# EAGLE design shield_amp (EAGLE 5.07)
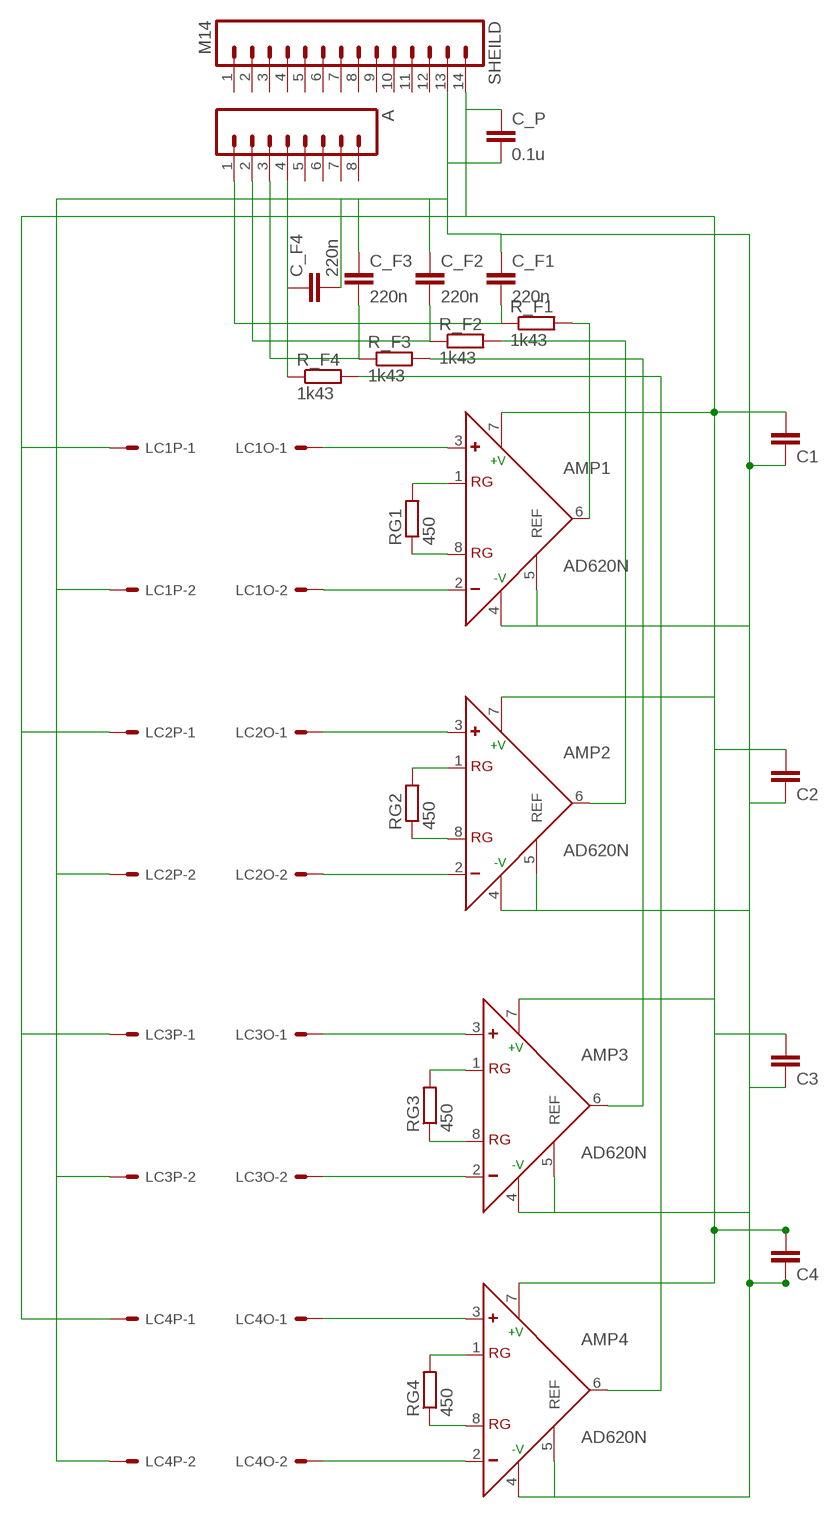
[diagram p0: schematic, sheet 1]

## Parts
A  M081X08  [1X08]
AMP1  AD620N  [DIL08]
AMP2  AD620N  [DIL08]
AMP3  AD620N  [DIL08]
AMP4  AD620N  [DIL08]
C1  C-EUC0603  [C0603]
C2  C-EUC0603  [C0603]
C3  C-EUC0603  [C0603]
C4  C-EUC0603  [C0603]
C_F1  220n  C-EU025-024X044  [C025-024X044]
C_F2  220n  C-EU025-024X044  [C025-024X044]
C_F3  220n  C-EU025-024X044  [C025-024X044]
C_F4  220n  C-EU025-024X044  [C025-024X044]
C_P  0.1u  C-EU025-024X044  [C025-024X044]
LC1O  87758-0216  [87758-0216]
LC1P  87758-0216  [87758-0216]
LC2O  87758-0216  [87758-0216]
LC2P  87758-0216  [87758-0216]
LC3O  87758-0216  [87758-0216]
LC3P  87758-0216  [87758-0216]
LC4O  87758-0216  [87758-0216]
LC4P  87758-0216  [87758-0216]
R_F1  1k43  R-EU_0207/7  [0207/7]
R_F2  1k43  R-EU_0207/7  [0207/7]
R_F3  1k43  R-EU_0207/7  [0207/7]
R_F4  1k43  R-EU_0207/7  [0207/7]
RG1  450  R-EU_0207/7  [0207/7]
RG2  450  R-EU_0207/7  [0207/7]
RG3  450  R-EU_0207/7  [0207/7]
RG4  450  R-EU_0207/7  [0207/7]
SHEILD  M14  [1X14]

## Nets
GND: AMP1.4(-V) AMP1.5(REF) AMP2.4(-V) AMP2.5(REF) AMP3.4(-V) AMP3.5(REF) AMP4.4(-V) AMP4.5(REF) C1.1 C2.1 C3.1 C4.1 C_F1.1 C_F2.1 C_F3.1 C_F4.2 C_P.2 LC1P.2 LC2P.2 LC3P.2 LC4P.2 SHEILD.13
N$1: AMP1.1(RG) RG1.2
N$2: AMP1.3(+) LC1O.1
N$3: AMP1.8(RG) RG1.1
N$4: AMP1.2(-) LC1O.2
N$5: AMP2.3(+) LC2O.1
N$6: AMP2.1(RG) RG2.2
N$7: AMP2.8(RG) RG2.1
N$8: AMP2.2(-) LC2O.2
N$9: AMP3.3(+) LC3O.1
N$10: AMP3.1(RG) RG3.2
N$11: AMP3.8(RG) RG3.1
N$12: AMP3.2(-) LC3O.2
N$13: AMP4.3(+) LC4O.1
N$14: AMP4.1(RG) RG4.2
N$15: AMP4.8(RG) RG4.1
N$16: AMP4.2(-) LC4O.2
N$17: AMP1.6(OUT) R_F1.2
N$18: AMP2.6(OUT) R_F2.2
N$19: AMP3.6(OUT) R_F3.2
N$20: AMP4.6(OUT) R_F4.2
N$21: AMP1.7(+V) AMP2.7(+V) AMP3.7(+V) AMP4.7(+V) C1.2 C2.2 C3.2 C4.2 C_P.1 LC1P.1 LC2P.1 LC3P.1 LC4P.1 SHEILD.14
N$22: A.3 C_F3.2 R_F3.1
N$23: A.1 C_F1.2 R_F1.1
N$25: A.2 C_F2.2 R_F2.1
N$26: A.4 C_F4.1 R_F4.1
Unconnected: A.5 A.6 A.7 A.8 SHEILD.1 SHEILD.2 SHEILD.3 SHEILD.4 SHEILD.5 SHEILD.6 SHEILD.7 SHEILD.8 SHEILD.9 SHEILD.10 SHEILD.11 SHEILD.12

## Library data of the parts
A = SparkFun:M08: Header 8 Standard 8-pin 0.1" header. Use with straight break away headers (SKU : PRT-00116), right angle break away headers (PRT-00553), swiss pins (PRT-00743), machine pins (PRT-00117), and female headers (PRT-00115).
AMP1-AMP4 = analog-devices:AD620: Low Cost, Low Power, Instrumentation Amplifier Source: http://www.analog.com/UploadedFiles/Data_Sheets/37793330023930AD620_e.pdf
C1-C4 C_F1-C_F4 C_P = resistor:C-EU: CAPACITOR, European symbol
LC1O LC1P LC2O LC2P LC3O LC3P LC4O LC4P = con-molex:87758-0216: 2 Pin - 2mm Dual Row Single Wafer, Vertical T/H HDR
R_F1-R_F4 RG1-RG4 = resistor:R-EU_: RESISTOR, European symbol
SHEILD = SparkFun:M14: Header 14 Standard 14-pin 0.1" header. Use with straight break away headers (SKU : PRT-00116), right angle break away headers (PRT-00553), swiss pins (PRT-00743), machine pins (PRT-00117), and female headers (PRT-00115).

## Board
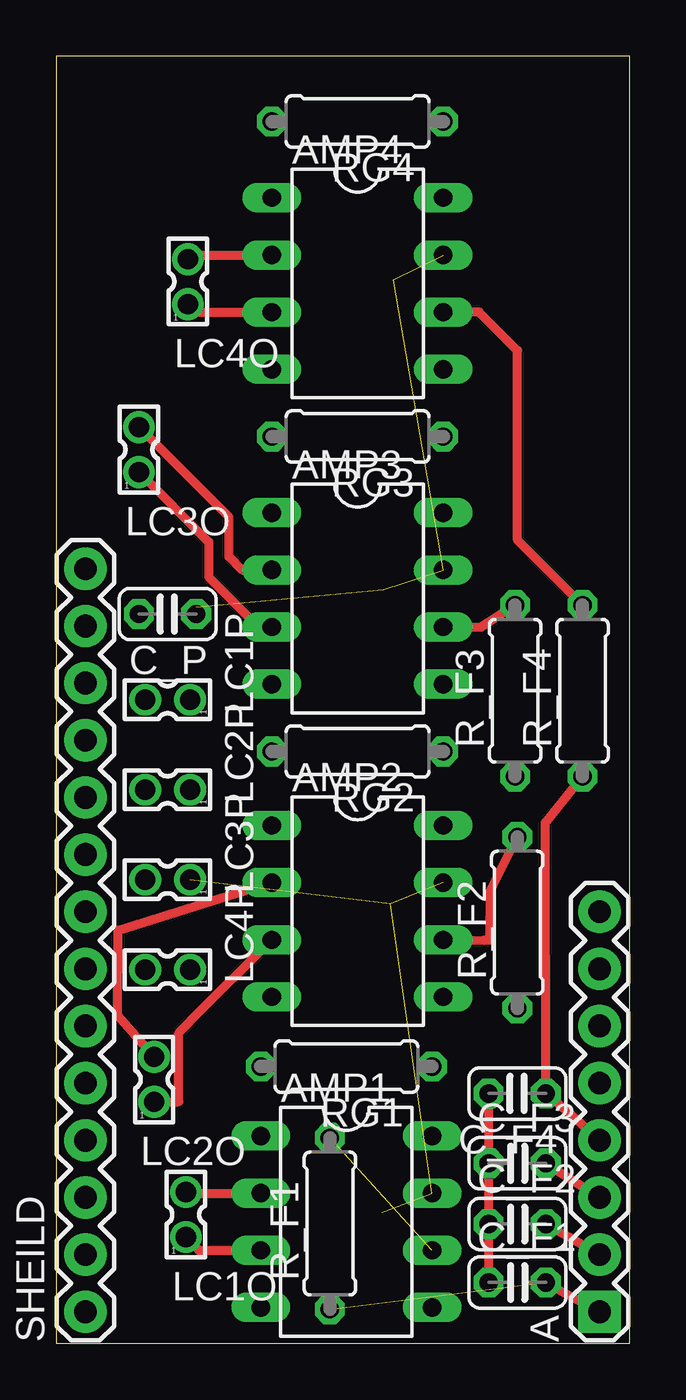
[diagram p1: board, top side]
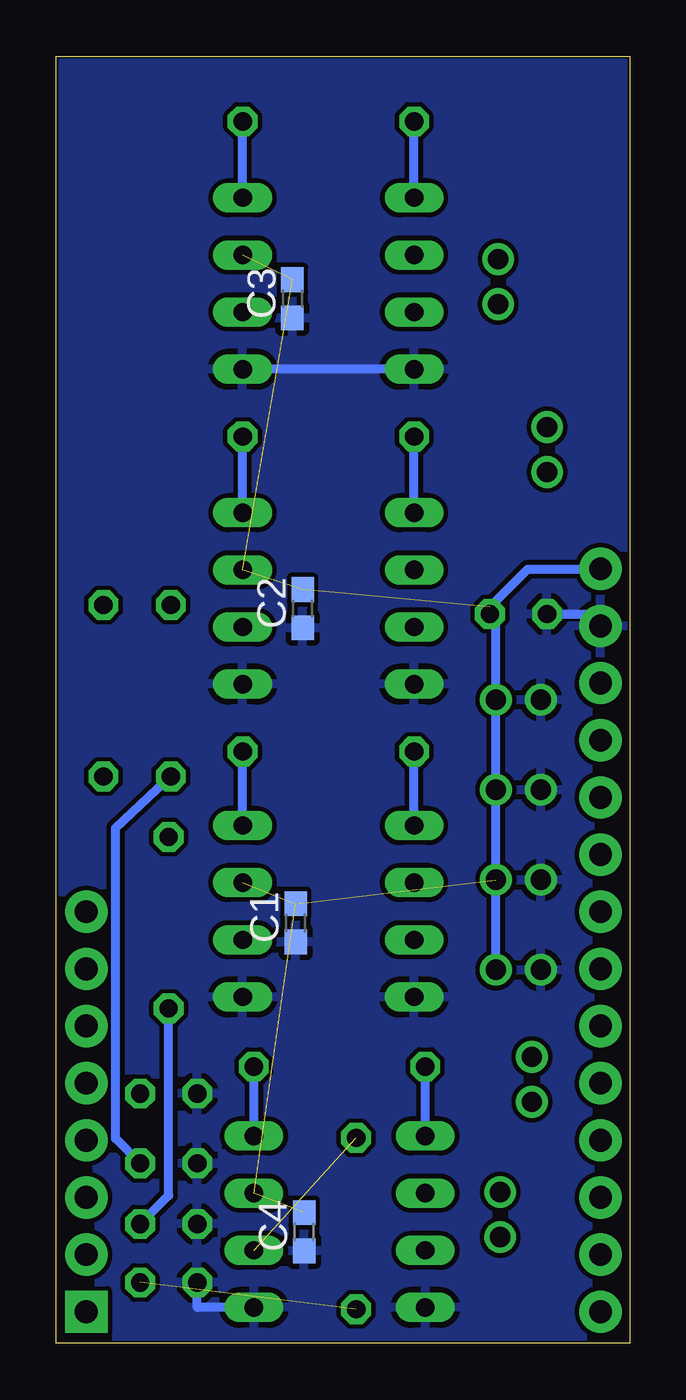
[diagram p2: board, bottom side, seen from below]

Size 25.5 x 57.2 mm. Coordinates in mm from the lower left corner, seen from the top.
Outline: 0,0 25.5,0 25.5,57.2 0,57.2 0,0
Copper layers (1*16): Top 0.035mm / dielectric 1.5mm / Bottom 0.035mm
Design rules "default *": minimum track width 10mil, minimum drill 24mil, track to track 8mil, track to pad 8mil, pad to pad 8mil, via to via 8mil, smd to smd 8mil, copper to edge 4mil, drill to drill 8mil, minimum pad ring 10mil, minimum via ring 8mil, stop-mask expansion 4mil, vias tented up to drill 0mil, thermal gap 10mil

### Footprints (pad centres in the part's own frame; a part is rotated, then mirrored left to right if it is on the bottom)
1X08 = drill 1.016 pad 1.88 square: 1 0,0 | drill 1.016 pad 1.88 round: 2 2.54,0; 3 5.08,0; 4 7.62,0; 5 10.16,0; 6 12.7,0; 7 15.24,0; 8 17.78,0
DIL08 = drill 0.813 long: 1 -3.81,-3.81; 2 -1.27,-3.81; 3 1.27,-3.81; 4 3.81,-3.81; 5 3.81,3.81; 6 1.27,3.81; 7 -1.27,3.81; 8 -3.81,3.81
C0603 = smd 1.1 x 1: 1 -0.85,0; 2 0.85,0
C025-024X044 = drill 0.813 octagon: 1 -1.27,0; 2 1.27,0
87758-0216 = drill 0.9 pad 1.27 round: 1 0,-1; 2 0,1
0207/7 = drill 0.813 octagon: 1 -3.81,0; 2 3.81,0
1X14 = drill 1.016 pad 1.88 round: 1 0,0; 2 2.54,0; 3 5.08,0; 4 7.62,0; 5 10.16,0; 6 12.7,0; 7 15.24,0; 8 17.78,0; 9 20.32,0; 10 22.86,0; 11 25.4,0; 12 27.94,0; 13 30.48,0; 14 33.02,0

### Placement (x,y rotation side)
A  24.16,1.4 90 top
AMP1  12.9,5.4 270 top
AMP2  13.4,19.2 270 top
AMP3  13.4,33.1 270 top
AMP4  13.4,47.1 270 top
C1  14.86,18.68 90 bottom
C2  14.54,32.65 90 bottom
C3  14.99,46.42 90 bottom
C4  14.48,4.96 90 bottom
C_F1  20.5,2.7 0 top
C_F2  20.5,5.3 0 top
C_F3  20.5,8 0 top
C_F4  20.5,11.1 180 top
C_P  4.95,32.41 180 top
LC1O  5.76,5.72 0 top
LC1P  4.95,28.6 90 top
LC2O  4.36,11.73 0 top
LC2P  4.95,24.6 90 top
LC3O  3.68,39.72 0 top
LC3P  4.95,20.6 90 top
LC4O  5.85,47.19 0 top
LC4P  4.95,16.6 90 top
R_F1  12.17,5.32 90 top
R_F2  20.5,18.69 90 top
R_F3  20.4,29 90 top
R_F4  23.4,29 90 top
RG1  12.9,12.3 180 top
RG2  13.4,26.3 180 top
RG3  13.4,40.3 180 top
RG4  13.4,54.3 180 top
SHEILD  1.3,1.4 90 top

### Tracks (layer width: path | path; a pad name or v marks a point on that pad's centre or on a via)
GND
  Top 0.406: C_F4.2 C_F3.1 C_F2.1 C_F1.1
  Bottom 0.406: AMP4.4 AMP4.5 | AMP1.5 19.23,1.59 C_F1.1 | SHEILD.13 1.83,32.41 C_P.2
  pour Bottom: -0.99,57.87 -1.12,57.87 -1.12,-1.16 26.14,-1.16 26.14,57.74
N$1
  Bottom 0.406: AMP1.1 RG1.2
N$2
  Top 0.406: LC1O.1 6.35,4.13 AMP1.3
N$3
  Bottom 0.406: AMP1.8 RG1.1
N$4
  Top 0.406: LC1O.2 5.81,6.67 AMP1.2
N$5
  Top 0.406: LC2O.1 5.45,10.74 5.44,13.79 6.49,14.87 9.15,17.5 AMP2.3
N$6
  Bottom 0.406: AMP2.1 RG2.2
N$7
  Bottom 0.406: AMP2.8 RG2.1
N$8
  Top 0.406: LC2O.2 2.73,14.56 2.75,18.35 8.42,20.12 AMP2.2
N$9
  Top 0.406: LC3O.1 6.78,35.62 6.78,34.06 9,31.83 AMP3.3
N$10
  Bottom 0.406: AMP3.1 RG3.2
N$11
  Bottom 0.406: AMP3.8 RG3.1
N$12
  Top 0.406: LC3O.2 7.68,36.72 7.68,34.96 8.27,34.37 AMP3.2
N$13
  Top 0.406: LC4O.1 6.21,45.83 AMP4.3
N$14
  Bottom 0.406: AMP4.1 RG4.2
N$15
  Bottom 0.406: AMP4.8 RG4.1
N$16
  Top 0.406: LC4O.2 6.04,48.37 AMP4.2
N$17  (1 unrouted)
N$18
  Top 0.406: R_F2.2 19.3,20.09 19.28,17.92 19.02,17.91 AMP2.6
N$19
  Top 0.406: R_F3.2 18.89,31.83 AMP3.6
N$20
  Top 0.406: R_F4.2 20.51,35.7 20.51,44.12 18.8,45.83 AMP4.6
N$21  (8 unrouted)
  Bottom 0.406: SHEILD.14 1.31,34.41 4.54,34.41 6.22,32.73 C_P.1 5.95,32.14 LC1P.1 LC2P.1 LC3P.1 LC4P.1
N$22
  Top 0.406: A.3 22.81,7.34 C_F3.2
  Bottom 0.406: C_F3.2 22.87,9.1 22.87,22.89 21.02,24.63 R_F3.1
N$23  (1 unrouted)
  Top 0.406: C_F1.2 22.63,2.23 A.1
N$25
  Top 0.406: A.2 22.8,4.72 C_F2.2
  Bottom 0.406: C_F2.2 20.5,6.57 R_F2.1
N$26
  Top 0.406: A.4 22.92,10.12 C_F4.1 21.76,11.39 21.74,23.13 22.88,24.54 R_F4.1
